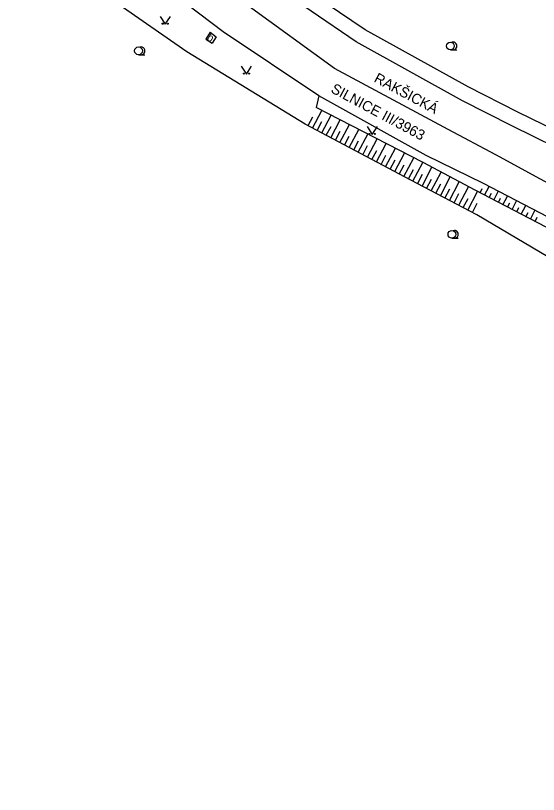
# Model space of a CAD drawing. Extents: x -621516 to -621304, y -1175233 to -1174899.
# Drawn here: x -621475.9 to -621425.3, y -1175077 to -1175001.6 of the extents above; entities that cross this region are included whole.
import ezdxf

# ---------------------------------------------------------------- set-up
doc = ezdxf.new("R2010")
doc.units = 0
for name, color, linetype in [('Názvy', 7, 'Continuous'), ('Pomocné popisy', 7, 'Continuous'), ('Rozhraní ploch', 7, 'Continuous'), ('Výškopis', 7, 'Continuous'), ('Značky kultur', 7, 'Continuous')]:
    doc.layers.add(name, color=color, linetype=linetype)

msp = doc.modelspace()

# ---------------------------------------------------------------- linework, layer by layer
at = {"layer": 'Rozhraní ploch'}
for p, q in [((-621457.07, -1175003.2), (-621457.49, -1175003.86)), ((-621457.07, -1175003.2), (-621456.49, -1175003.66)), ((-621457.49, -1175003.86), (-621456.87, -1175004.26)), ((-621456.49, -1175003.66), (-621456.87, -1175004.26)), ((-621413.91, -1175017.52), (-621427.27, -1175010.93))]:
    msp.add_line(p, q, dxfattribs=at)
for points in [[(-621429.4, -1175015.08), (-621434.02, -1175012.61), (-621445.03, -1175006.72), (-621453.4, -1175000.63), (-621464.84, -1174992.19), (-621474.13, -1174981.86)], [(-621430.6, -1175017.86), (-621436.15, -1175015.14), (-621446.55, -1175009.36), (-621455.81, -1175003.15), (-621466.19, -1174995.3), (-621469.34, -1174992.69), (-621473.84, -1174987.89), (-621475.92, -1174984.77)], [(-621427.27, -1175010.93), (-621432.07, -1175008.49), (-621442.06, -1175002.97), (-621450.8, -1174997.02), (-621455.95, -1174993.25), (-621459.98, -1174989.87)], [(-621421.41, -1175015.41), (-621427.83, -1175012.26), (-621432.62, -1175009.84), (-621442.92, -1175004.13), (-621451.63, -1174998.17), (-621460.93, -1174990.89)], [(-621334.61, -1175169.74), (-621337.93, -1175156.21), (-621341.04, -1175144), (-621345.71, -1175128.29), (-621348.52, -1175118.58), (-621351.83, -1175109.02), (-621355.96, -1175097.53), (-621358.67, -1175090.23), (-621362.68, -1175082.07), (-621365.02, -1175076.44), (-621372.11, -1175064.96), (-621377.05, -1175056.97), (-621383.6, -1175047.36), (-621391.59, -1175039.63), (-621400.61, -1175030.85), (-621405.51, -1175027.13), (-621416.77, -1175021.96), (-621429.4, -1175015.08)], [(-621361.69, -1175091.69), (-621365.44, -1175083.96), (-621368.23, -1175078.24), (-621375.16, -1175066.17), (-621380.05, -1175058.81), (-621386.57, -1175050.21), (-621393.72, -1175042.33), (-621400.36, -1175035.83), (-621402.49, -1175033.96), (-621407.21, -1175030.49), (-621418.07, -1175024.36), (-621430.6, -1175017.86)]]:
    msp.add_lwpolyline(points, dxfattribs=at)
at = {"layer": 'Výškopis'}
for p, q in [((-621446.55, -1175009.36), (-621446.79, -1175010.49)), ((-621447.138, -1175012.478), (-621446.235, -1175010.776)), ((-621447.58, -1175012.243), (-621447.13, -1175011.395)), ((-621446.697, -1175012.712), (-621446.244, -1175011.858)), ((-621446.255, -1175012.947), (-621445.346, -1175011.234)), ((-621445.372, -1175013.415), (-621444.457, -1175011.691)), ((-621445.814, -1175013.181), (-621445.358, -1175012.322)), ((-621444.489, -1175013.884), (-621443.568, -1175012.149)), ((-621443.605, -1175014.353), (-621442.679, -1175012.607)), ((-621444.93, -1175013.65), (-621444.471, -1175012.785)), ((-621444.047, -1175014.119), (-621443.585, -1175013.248)), ((-621442.722, -1175014.822), (-621441.79, -1175013.065)), ((-621443.164, -1175014.587), (-621442.699, -1175013.712)), ((-621441.839, -1175015.291), (-621440.9, -1175013.523)), ((-621440.956, -1175015.76), (-621440.011, -1175013.981)), ((-621442.28, -1175015.056), (-621441.813, -1175014.175)), ((-621441.397, -1175015.525), (-621440.927, -1175014.639)), ((-621440.072, -1175016.228), (-621439.122, -1175014.439)), ((-621440.514, -1175015.994), (-621440.04, -1175015.102)), ((-621439.631, -1175016.463), (-621439.154, -1175015.565)), ((-621439.189, -1175016.697), (-621438.233, -1175014.897)), ((-621438.306, -1175017.166), (-621437.344, -1175015.354)), ((-621438.747, -1175016.932), (-621438.268, -1175016.029)), ((-621437.422, -1175017.634), (-621436.466, -1175015.807)), ((-621436.536, -1175018.098), (-621435.582, -1175016.276)), ((-621437.864, -1175017.4), (-621437.382, -1175016.492)), ((-621436.979, -1175017.866), (-621436.501, -1175016.953)), ((-621435.65, -1175018.561), (-621434.699, -1175016.746)), ((-621436.093, -1175018.329), (-621435.617, -1175017.42)), ((-621435.207, -1175018.793), (-621434.732, -1175017.887)), ((-621434.764, -1175019.025), (-621433.816, -1175017.215)), ((-621433.878, -1175019.489), (-621432.934, -1175017.685)), ((-621434.321, -1175019.257), (-621433.848, -1175018.353)), ((-621432.992, -1175019.953), (-621432.051, -1175018.154)), ((-621432.106, -1175020.416), (-621431.167, -1175018.622)), ((-621430.917, -1175018.752), (-621430.701, -1175018.336)), ((-621430.474, -1175018.983), (-621430.04, -1175018.15)), ((-621429.587, -1175019.444), (-621429.153, -1175018.611)), ((-621433.435, -1175019.721), (-621432.963, -1175018.82)), ((-621432.549, -1175020.184), (-621432.079, -1175019.287)), ((-621430.03, -1175019.213), (-621429.813, -1175018.797)), ((-621429.143, -1175019.675), (-621428.926, -1175019.258)), ((-621428.7, -1175019.906), (-621428.265, -1175019.071)), ((-621431.663, -1175020.648), (-621431.193, -1175019.75)), ((-621428.256, -1175020.137), (-621428.039, -1175019.719)), ((-621427.813, -1175020.368), (-621427.377, -1175019.532)), ((-621426.926, -1175020.83), (-621426.49, -1175019.992)), ((-621427.369, -1175020.599), (-621427.151, -1175020.181)), ((-621426.483, -1175021.061), (-621426.264, -1175020.642)), ((-621426.039, -1175021.292), (-621425.602, -1175020.453)), ((-621425.596, -1175021.523), (-621425.377, -1175021.103))]:
    msp.add_line(p, q, dxfattribs=at)
for points in [[(-621431.22, -1175020.88), (-621437.62, -1175017.53), (-621447.85, -1175012.1), (-621459.32, -1175005.1), (-621466.3, -1175000.26)], [(-621408.44, -1175030.79), (-621418.46, -1175025.24), (-621431.4, -1175018.5), (-621436.44, -1175015.82), (-621446.79, -1175010.49)], [(-621400.33, -1175039.51), (-621403.19, -1175037.28), (-621409.59, -1175032.33), (-621418.2, -1175028.58), (-621431.22, -1175020.88)]]:
    msp.add_lwpolyline(points, dxfattribs=at)
at = {"layer": 'Značky kultur'}
for p, q in [((-621433.79, -1175004.905), (-621433.165, -1175004.905)), ((-621464.01, -1175005.375), (-621463.385, -1175005.375)), ((-621433.65, -1175023.145), (-621433.025, -1175023.145))]:
    msp.add_line(p, q, dxfattribs=at)
for points in [[(-621461.92, -1175001.67), (-621461.42, -1175002.42), (-621460.92, -1175001.67)], [(-621454.05, -1175006.5), (-621453.55, -1175007.25), (-621453.05, -1175006.5)], [(-621441.87, -1175012.34), (-621441.37, -1175013.09), (-621440.87, -1175012.34)]]:
    msp.add_lwpolyline(points, dxfattribs=at)
for centre, radius in [((-621461.67, -1175002.37), 0.05), ((-621461.17, -1175002.37), 0.05), ((-621433.79, -1175004.53), 0.375), ((-621464.01, -1175005), 0.375), ((-621453.8, -1175007.2), 0.05), ((-621453.3, -1175007.2), 0.05), ((-621441.62, -1175013.04), 0.05), ((-621441.12, -1175013.04), 0.05), ((-621433.65, -1175022.77), 0.375)]:
    msp.add_circle(centre, radius, dxfattribs=at)
for centre in [(-621433.54, -1175004.53), (-621463.76, -1175005), (-621433.4, -1175022.77)]:
    msp.add_arc(centre, 0.375, 249.49437, 109.04743, dxfattribs=at)

# ---------------------------------------------------------------- texts
at = {"layer": 'Názvy'}
for s, p in [('RAKŠICKÁ', (-621441.28, -1175007.96)), ('SILNICE III/3963', (-621445.45, -1175008.98))]:
    msp.add_text(s, height=1, rotation=331.85, dxfattribs=at).set_placement(p)
at = {"layer": 'Pomocné popisy'}
msp.add_text('b.', height=0.75, rotation=327.17146, dxfattribs=at).set_placement((-621457.46, -1175003.88))

doc.saveas('drawing.dxf')
